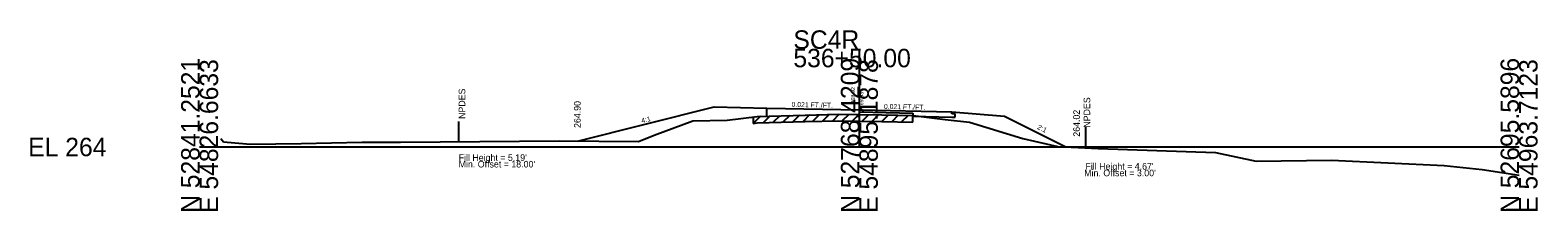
# Model space of a CAD drawing. Extents: x 7498 to 13027, y 90095 to 109625.
# Drawn here: x 9498.3 to 9726.8, y 106595.5 to 106622.9 of the extents above; entities that cross this region are included whole.
import ezdxf

# ---------------------------------------------------------------- set-up
doc = ezdxf.new("R2010")
doc.units = 0
for name, color, linetype in [('Level 10', 7, 'Continuous'), ('Level 11', 7, 'Continuous'), ('Level 12', 7, 'Continuous'), ('Level 32', 7, 'Continuous'), ('Level 33', 7, 'Continuous'), ('Level 50', 7, 'Continuous'), ('Level 53', 7, 'Continuous'), ('Level 55', 7, 'Continuous'), ('Level 59', 7, 'Continuous'), ('Level 6', 7, 'Continuous'), ('Level 60', 7, 'Continuous'), ('Level 61', 7, 'Continuous'), ('Level 63', 7, 'Continuous'), ('Level 7', 7, 'Continuous')]:
    doc.layers.add(name, color=color, linetype=linetype)

msp = doc.modelspace()

# ---------------------------------------------------------------- linework, layer by layer
at = {"layer": 'Level 11'}
for p, q in [((9609.99, 106609.85), (9609.99, 106611.07)), ((9637.99, 106610.19), (9637.99, 106610.49)), ((9638.49, 106610.18), (9637.99, 106610.19)), ((9638.49, 106609.7), (9638.49, 106610.18)), ((9637.99, 106609.71), (9638.49, 106609.7))]:
    msp.add_line(p, q, dxfattribs=at)
at = {"layer": 'Level 12'}
for p, q in [((9632.1, 106609.93), (9632.1, 106609.83)), ((9632.1, 106609.83), (9637.99, 106609.71))]:
    msp.add_line(p, q, dxfattribs=at)
at = {"layer": 'Level 53'}
for p, q in [((9623.99, 106610.48), (9632.1, 106610.31)), ((9632.1, 106610.31), (9632.1, 106609.93))]:
    msp.add_line(p, q, dxfattribs=at)
at = {"layer": 'Level 55'}
for p, q in [((9563.25, 106609.05), (9563.25, 106606.05)), ((9658.3, 106605.17), (9658.3, 106608.17))]:
    msp.add_line(p, q, dxfattribs=at)
at = {"layer": 'Level 59'}
for p, q in [((9609.99, 106611.07), (9623.99, 106610.78)), ((9623.99, 106610.78), (9637.99, 106610.49))]:
    msp.add_line(p, q, dxfattribs=at)
at = {"layer": 'Level 6'}
for p, q in [((9601.99, 106611.24), (9609.99, 106611.07)), ((9637.99, 106610.49), (9645.99, 106609.82))]:
    msp.add_line(p, q, dxfattribs=at)
at = {"layer": 'Level 60'}
for p, q in [((9608.52, 106609.81), (9615.76, 106610.01)), ((9615.76, 106610.01), (9620.88, 106610.12)), ((9620.88, 106610.12), (9623.99, 106610.07)), ((9623.99, 106610.07), (9627.41, 106610.02)), ((9627.41, 106610.02), (9632.15, 106609.93)), ((9632.15, 106609.93), (9637.02, 106609.34)), ((9592.9, 106606.96), (9598.77, 106609.14)), ((9598.77, 106609.14), (9603.94, 106609.24)), ((9603.94, 106609.24), (9608.52, 106609.81)), ((9637.02, 106609.34), (9640.67, 106608.95)), ((9640.67, 106608.95), (9648.76, 106606.47)), ((9527.19, 106606.43), (9527.63, 106605.94)), ((9527.63, 106605.94), (9528.18, 106605.91)), ((9528.18, 106605.91), (9531.71, 106605.57)), ((9531.71, 106605.57), (9539.36, 106605.7)), ((9539.36, 106605.7), (9548.56, 106605.9)), ((9548.56, 106605.9), (9554.43, 106605.87)), ((9554.43, 106605.87), (9578.47, 106606.07)), ((9578.47, 106606.07), (9590.5, 106606)), ((9590.5, 106606), (9592.9, 106606.96)), ((9648.76, 106606.47), (9654.06, 106605.23)), ((9654.06, 106605.23), (9660.2, 106604.94)), ((9660.2, 106604.94), (9677.96, 106604.31)), ((9677.96, 106604.31), (9684.12, 106603.01)), ((9684.12, 106603.01), (9695.55, 106603.18)), ((9695.55, 106603.18), (9712.65, 106602.33)), ((9712.65, 106602.33), (9718.39, 106601.76)), ((9718.39, 106601.76), (9723.99, 106600.89))]:
    msp.add_line(p, q, dxfattribs=at)
at = {"layer": 'Level 61'}
for p, q in [((9613.43, 106609.95), (9612.4, 106608.92)), ((9614.93, 106609.99), (9613.9, 106608.96)), ((9616.42, 106610.03), (9615.4, 106609)), ((9617.92, 106610.06), (9616.9, 106609.04)), ((9619.42, 106610.09), (9618.4, 106609.07)), ((9620.92, 106610.12), (9619.9, 106609.1)), ((9622.39, 106610.1), (9621.4, 106609.12)), ((9623.89, 106610.08), (9622.9, 106609.09)), ((9625.39, 106610.05), (9624.4, 106609.07)), ((9626.89, 106610.03), (9625.9, 106609.04)), ((9628.38, 106610), (9627.4, 106609.02)), ((9629.89, 106609.97), (9628.9, 106608.99)), ((9631.39, 106609.94), (9630.4, 106608.96)), ((9632.1, 106608.93), (9632.1, 106609.93)), ((9608.99, 106609.82), (9607.9, 106608.73)), ((9607.9, 106609.73), (9607.9, 106608.73)), ((9607.9, 106608.73), (9608.52, 106608.81)), ((9608.52, 106608.81), (9615.76, 106609.01)), ((9610.43, 106609.86), (9609.4, 106608.83)), ((9611.93, 106609.9), (9610.9, 106608.87)), ((9615.76, 106609.01), (9620.88, 106609.12)), ((9620.88, 106609.12), (9623.99, 106609.07)), ((9623.99, 106609.07), (9627.41, 106609.02)), ((9627.41, 106609.02), (9632.1, 106608.93))]:
    msp.add_line(p, q, dxfattribs=at)
at = {"layer": 'Level 63'}
for p, q in [((9623.99, 106605.16), (9623.99, 106620.06)), ((9523.99, 106605.16), (9623.99, 106605.16)), ((9623.99, 106605.16), (9723.99, 106605.16))]:
    msp.add_line(p, q, dxfattribs=at)
at = {"layer": 'Level 7'}
for p, q in [((9581.25, 106606.05), (9601.99, 106611.24)), ((9645.99, 106609.82), (9655.3, 106605.17))]:
    msp.add_line(p, q, dxfattribs=at)

# ---------------------------------------------------------------- texts
at = {"layer": 'Level 10'}
msp.add_text('268.92', height=0.6, rotation=90, dxfattribs=at).set_placement((9623.34, 106611.72))
at = {"layer": 'Level 32'}
for s, rotation, p in [('0.021 FT./FT.', 358.8084, (9613.71, 106611.25)), ('0.021 FT./FT.', 358.8084, (9627.71, 106610.95)), ('4:1', 14.0362, (9591.04, 106608.76)), ('2:1', 333.435, (9650.89, 106607.94))]:
    msp.add_text(s, height=0.75, rotation=rotation, dxfattribs=at).set_placement(p)
at = {"layer": 'Level 33'}
for s, p in [('264.90', (9581.75, 106608.05)), ('264.02', (9657.41, 106606.72))]:
    msp.add_text(s, height=1, rotation=90, dxfattribs=at).set_placement(p)
at = {"layer": 'Level 50'}
for p in [(9564.25, 106609.05), (9658.98, 106607.72)]:
    msp.add_text(' NPDES', height=1, rotation=90, dxfattribs=at).set_placement(p)
for s, p in [("Fill Height = 5.19' ", (9563.25, 106603.05)), ("Min. Offset = 18.00' ", (9563.25, 106602.05)), ("Min. Offset = 3.00' ", (9658.07, 106600.72)), ("Fill Height = 4.67' ", (9658.26, 106601.72))]:
    msp.add_text(s, height=1, dxfattribs=at).set_placement(p)
at = {"layer": 'Level 59'}
msp.add_text(' 269.63', height=0.6, rotation=90, dxfattribs=at).set_placement((9624.59, 106610.78))
at = {"layer": 'Level 63'}
for s, p in [('SC4R', (9613.99, 106620.06)), ('536+50.00', (9613.99, 106617.26)), ('EL 264', (9498, 106603.76))]:
    msp.add_text(s, height=2.8, dxfattribs=at).set_placement(p)
for s, p in [('N 52841.2521', (9523.99, 106595.16)), ('E 54826.6633', (9526.79, 106595.16)), ('N 52768.4209', (9623.99, 106595.16)), ('E 54895.1878', (9626.79, 106595.16)), ('N 52695.5896', (9723.99, 106595.16)), ('E 54963.7123', (9726.79, 106595.16))]:
    msp.add_text(s, height=2.8, rotation=90, dxfattribs=at).set_placement(p)

doc.saveas('drawing.dxf')
